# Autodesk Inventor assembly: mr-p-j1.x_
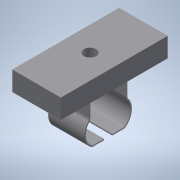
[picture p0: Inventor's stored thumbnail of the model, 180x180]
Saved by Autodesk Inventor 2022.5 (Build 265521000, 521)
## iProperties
Part Number: mr-p-j1.x_
Material: 一般
Document SubType Name: Assembly
Designer: ImaoCorp
Sending System: SOLIDWORKS 2017-2017317
MC: AMD64
MC_MODEL: Intel64 Family 6 Model 60 Stepping 3, GenuineIntel
OS: Windows_NT
FRU: Parasolid Version 29.0, build 201,  4-17-2017
FORMAT: text
GUISE: transmit
KEY: mr-p-j1
FILE: mr-p-j1.x_t
DATE: Fri Jul 26 11:48:54 2019
Author: ImaoCorp
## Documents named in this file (3)
- X:\14_SW2022-Inv2022\00_全2023-1023新製品(TCC)まで\m\mr-p-j1\MR-P-J1.iam
- X:\14_SW2022-Inv2022\00_全2023-1023新製品(TCC)まで\m\mr-p-j1\mr-p-j1_01.ipt
- X:\14_SW2022-Inv2022\00_全2023-1023新製品(TCC)まで\m\mr-p-j1\mr-p-j1_02.ipt
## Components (2 placed, 2 different names)
1. mr-p-j1_01
2. mr-p-j1_02
